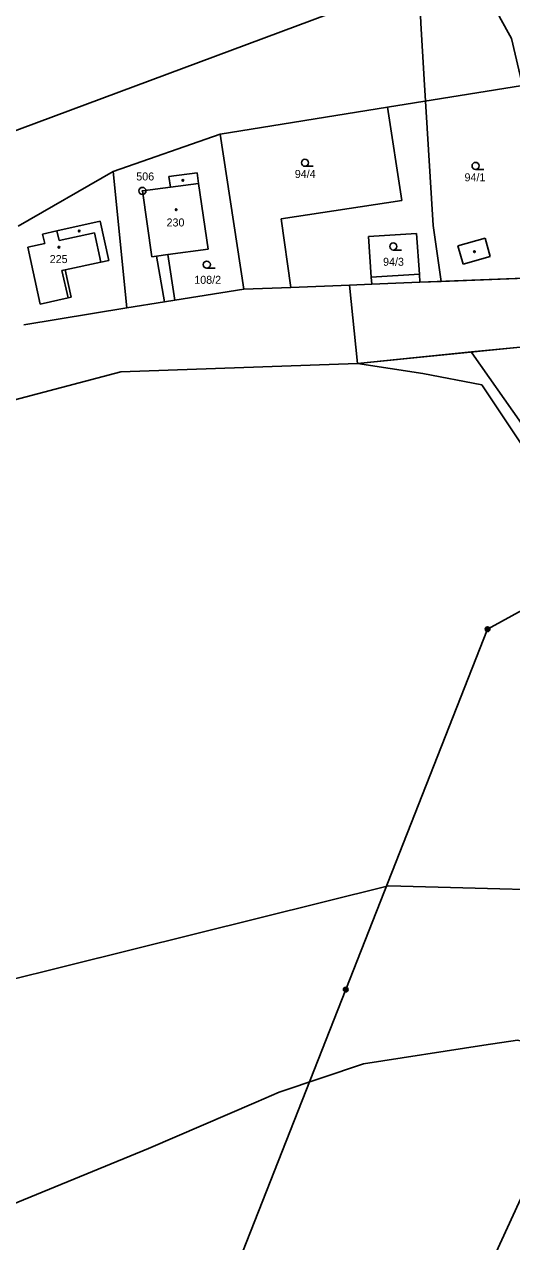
# Model space of a CAD drawing. Extents: x -725765 to -723182, y -1052705 to -1049154.
# Drawn here: x -725049.2 to -724945.7, y -1050771.8 to -1050513.3 of the extents above; entities that cross this region are included whole.
import ezdxf

# ---------------------------------------------------------------- set-up
doc = ezdxf.new("R2010")
doc.units = 0
for name, color, linetype in [('Vrstva 1', 7, 'Continuous'), ('Vrstva 12', 7, 'Continuous'), ('Vrstva 17', 7, 'Continuous'), ('Vrstva 18', 7, 'Continuous'), ('Vrstva 19', 7, 'Continuous'), ('Vrstva 25', 7, 'Continuous'), ('Vrstva 4', 7, 'Continuous'), ('Vrstva 52', 7, 'Continuous')]:
    doc.layers.add(name, color=color, linetype=linetype)

msp = doc.modelspace()

# ---------------------------------------------------------------- linework, layer by layer
at = {"layer": 'Vrstva 1'}
for points in [[(-724953.68, -1050499.49), (-725166.88, -1050578.89)], [(-724945.76, -1050516.26), (-724948.28, -1050511.7)], [(-724943.41, -1050526.29), (-724945.76, -1050516.26)], [(-724972.12, -1050530.88), (-724943.41, -1050526.29)], [(-725007.67, -1050536.57), (-724972.12, -1050530.88)], [(-724969.08, -1050550.65), (-724972.12, -1050530.88)], [(-725007.67, -1050536.57), (-725030.33, -1050544.55)], [(-725007.67, -1050536.57), (-725002.6, -1050569.51)], [(-725030.33, -1050544.55), (-725050.55, -1050556.14)], [(-725030.33, -1050544.55), (-725027.43, -1050573.46)], [(-725024.15, -1050548.64), (-725018.21, -1050547.86)], [(-725018.21, -1050547.86), (-725012.21, -1050547.08)], [(-725012.21, -1050547.08), (-725010.21, -1050560.98)], [(-725024.15, -1050548.64), (-725022.13, -1050562.64)], [(-724994.65, -1050554.59), (-724969.08, -1050550.65)], [(-725042.32, -1050557.14), (-725033.13, -1050555.06)], [(-725033.13, -1050555.06), (-725031.28, -1050563.41)], [(-724992.61, -1050569.12), (-724994.65, -1050554.59)], [(-725045.35, -1050557.82), (-725042.32, -1050557.14)], [(-725045.35, -1050557.82), (-725044.9, -1050559.81)], [(-724976.12, -1050558.31), (-724965.92, -1050557.66)], [(-724976.12, -1050558.31), (-724975.55, -1050566.95)], [(-724965.92, -1050557.66), (-724965.33, -1050566.3)], [(-725048.46, -1050560.56), (-725044.9, -1050559.81)], [(-725048.46, -1050560.56), (-725045.89, -1050572.71)], [(-725018.77, -1050562.17), (-725010.21, -1050560.98)], [(-725032.95, -1050563.76), (-725031.28, -1050563.41)], [(-725022.13, -1050562.64), (-725021.19, -1050562.51)], [(-725021.19, -1050562.51), (-725019.49, -1050572.2)], [(-725017.24, -1050571.84), (-725018.77, -1050562.17)], [(-725040.57, -1050565.38), (-725032.95, -1050563.76)], [(-725040.57, -1050565.38), (-725039.27, -1050571.18)], [(-724992.61, -1050569.12), (-724980.14, -1050568.64)], [(-724980.14, -1050568.64), (-724975.45, -1050568.46)], [(-724980.14, -1050568.64), (-724978.46, -1050585.27)], [(-724975.55, -1050566.95), (-724975.45, -1050568.46)], [(-724975.45, -1050568.46), (-724965.21, -1050568.05)], [(-724965.33, -1050566.3), (-724965.21, -1050568.05)], [(-724965.21, -1050568.05), (-724928.41, -1050566.61)], [(-725045.89, -1050572.71), (-725039.95, -1050571.34)], [(-725039.95, -1050571.34), (-725039.27, -1050571.18)], [(-725017.24, -1050571.84), (-725002.6, -1050569.51)], [(-725002.6, -1050569.51), (-724992.61, -1050569.12)], [(-725049.33, -1050577.06), (-725027.43, -1050573.46)], [(-725027.43, -1050573.46), (-725019.49, -1050572.2)], [(-725019.49, -1050572.2), (-725017.24, -1050571.84)], [(-724978.46, -1050585.27), (-724943.94, -1050581.79)], [(-725028.74, -1050587.06), (-724978.46, -1050585.27)], [(-724978.46, -1050585.27), (-724964.57, -1050587.44)], [(-725066.64, -1050597.04), (-725028.74, -1050587.06)], [(-724964.57, -1050587.44), (-724952.07, -1050589.8)], [(-724952.07, -1050589.8), (-724943.28, -1050602.98)], [(-724971.87, -1050696.18), (-725258.93, -1050767.53)], [(-724919.24, -1050697.62), (-724971.87, -1050696.18)]]:
    msp.add_lwpolyline(points, dxfattribs=at)
at = {"layer": 'Vrstva 12'}
for points in [[(-724950.85, -1050641.71), (-724890.28, -1050608.5)], [(-724980.97, -1050718.23), (-724950.85, -1050641.71)], [(-724980.97, -1050718.23), (-725012.16, -1050797.58)]]:
    msp.add_lwpolyline(points, dxfattribs=at)
at = {"layer": 'Vrstva 25'}
for points in [[(-724989.63, -1050543.42), (-724987.88, -1050543.42)], [(-724953.39, -1050544.08), (-724951.64, -1050544.08)], [(-724970.87, -1050561.19), (-724969.12, -1050561.19)], [(-725010.47, -1050565.05), (-725008.72, -1050565.05)]]:
    msp.add_lwpolyline(points, dxfattribs=at)
for centre, radius in [((-724989.63, -1050542.67), 0.75), ((-724953.39, -1050543.33), 0.75), ((-725024.15, -1050548.64), 0.75), ((-725015.56, -1050546.4), 0.175), ((-725024.15, -1050548.64), 0.032), ((-725016.98, -1050552.64), 0.175), ((-725037.58, -1050557.16), 0.175), ((-725041.89, -1050560.6), 0.175), ((-724970.87, -1050560.44), 0.75), ((-725010.47, -1050564.3), 0.75), ((-724953.63, -1050561.55), 0.175), ((-724950.85, -1050641.71), 0.5), ((-724950.85, -1050641.71), 0.3), ((-724950.85, -1050641.71), 0.15), ((-724980.97, -1050718.23), 0.5), ((-724980.97, -1050718.23), 0.3), ((-724980.97, -1050718.23), 0.15)]:
    msp.add_circle(centre, radius, dxfattribs=at)
at = {"layer": 'Vrstva 4'}
for points in [[(-725018.52, -1050545.61), (-725012.54, -1050544.78)], [(-725018.52, -1050545.61), (-725018.21, -1050547.86)], [(-725012.54, -1050544.78), (-725012.21, -1050547.08)], [(-725042.32, -1050557.14), (-725041.86, -1050559.15)], [(-725041.86, -1050559.15), (-725034.3, -1050557.51)], [(-725034.3, -1050557.51), (-725032.95, -1050563.76)], [(-724957.13, -1050560.31), (-724951.36, -1050558.71)], [(-724957.13, -1050560.31), (-724956.05, -1050564.19)], [(-724951.36, -1050558.71), (-724950.28, -1050562.59)], [(-725021.19, -1050562.51), (-725018.77, -1050562.17)], [(-724956.05, -1050564.19), (-724950.28, -1050562.59)], [(-725041.26, -1050565.53), (-725040.57, -1050565.38)], [(-725041.26, -1050565.53), (-725039.95, -1050571.34)], [(-724975.55, -1050566.95), (-724965.33, -1050566.3)]]:
    msp.add_lwpolyline(points, dxfattribs=at)
at = {"layer": 'Vrstva 52'}
for points in [[(-724962.55, -1050479.39), (-724962.88, -1050480), (-724965.81, -1050495), (-724965, -1050513), (-724964.31, -1050525), (-724964.03, -1050529.59), (-724962.38, -1050556), (-724960.72, -1050567.87)], [(-724960.72, -1050567.87), (-724928.41, -1050566.61), (-724922.05, -1050564.84), (-724927.41, -1050553.28), (-724925.99, -1050552.71), (-724927.71, -1050547.24), (-724931.58, -1050534.9), (-724936.56, -1050525.18), (-724931.9, -1050524.44), (-724937.51, -1050525.33), (-724939.48, -1050525.65), (-724943.41, -1050526.29), (-724945.76, -1050516.26), (-724948.28, -1050511.7), (-724953.68, -1050499.49), (-724962.55, -1050479.39)], [(-724960.72, -1050567.87), (-724965.21, -1050568.05), (-724975.45, -1050568.46), (-724980.14, -1050568.64), (-724978.46, -1050585.27), (-724954.28, -1050582.83)], [(-724954.28, -1050582.83), (-724943.94, -1050581.79), (-724925.4, -1050585.31), (-724896.53, -1050598.91), (-724892.98, -1050592.12), (-724870.23, -1050606.2)], [(-724954.28, -1050582.83), (-724954.19, -1050583), (-724943.63, -1050598), (-724929.31, -1050611), (-724914.88, -1050620), (-724901.88, -1050625), (-724890.38, -1050626), (-724884.61, -1050625.3), (-724882.19, -1050625), (-724876.38, -1050620), (-724871.63, -1050613), (-724870.23, -1050606.2)], [(-725008.87, -1050841.99), (-725004.69, -1050838), (-725000, -1050833.49), (-724982.88, -1050817), (-724968.81, -1050803), (-724956.13, -1050787), (-724949, -1050774), (-724939.38, -1050753), (-724937.5, -1050742), (-724937.5, -1050735), (-724940.13, -1050730), (-724944.5, -1050729), (-724951.63, -1050730), (-724977.19, -1050734), (-724995.13, -1050740), (-725000, -1050742.11), (-725022.88, -1050752), (-725054.63, -1050765)]]:
    msp.add_lwpolyline(points, dxfattribs=at)

# ---------------------------------------------------------------- texts
at = {"layer": 'Vrstva 17'}
msp.add_text('506', height=1.7, dxfattribs=at).set_placement((-725025.45, -1050546.42))
at = {"layer": 'Vrstva 18'}
for s, p in [('94/4', (-724991.78, -1050545.89)), ('94/1', (-724955.73, -1050546.6)), ('94/3', (-724973.03, -1050564.54)), ('108/2', (-725013.13, -1050568.37))]:
    msp.add_text(s, height=1.7, dxfattribs=at).set_placement(p)
at = {"layer": 'Vrstva 19'}
for s, p in [('230', (-725019.02, -1050556.19)), ('225', (-725043.84, -1050563.97))]:
    msp.add_text(s, height=1.7, dxfattribs=at).set_placement(p)

doc.saveas('drawing.dxf')
